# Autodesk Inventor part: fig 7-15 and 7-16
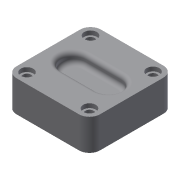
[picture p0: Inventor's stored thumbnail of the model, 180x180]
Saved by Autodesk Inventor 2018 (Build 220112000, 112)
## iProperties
Shininess: 77.0
Angle Display Precision: 2
Document Length Units: 11269
Document Angle Units: 11279
Document Time Units: 11290
Document Mass Units: 11283
Document Length Units Precision: 3
Document Angle Units Precision: 2
Created: 2001-12
Part Number: fig 7-15 and 7-16
Document SubType Name: Modeling
Designer: Renu Muthoo
Density: 1 g/cm^3
Material: Generic
Appearance: Default
Density: 0.0
Volumn: 0.0
Area: 0.0
PropertySet Name: Model Information
Control State: 0
Master: False
Checked Out: False
Author: Renu Muthoo
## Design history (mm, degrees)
sketch "Sketch1"
  geometry: L1 (-20, 20)-(20, 20); L2 (20, 20)-(20, -20.5); L3 (20, -20.5)-(-20, -20.5); L4 (-20, -20.5)-(-20, 20); 1 further point
  constraints: 8 end point, 2 parallel, 1 horizontal, 1 perpendicular, 1 other
  dimensions: "d0" = 40 distance of L1.start L1.end; "d1" = 40.5 distance of L3.end L1.start; "d100" = 20 distance from line of L4 point (0, 0); "d101" = 20 distance from line of L1 point (0, 0)
extrude "Extrusion1" new body sketch "Sketch1" distance "d2" = 15; taper "d3" = 0 deg
workplane "Work Plane1"
workplane "Work Plane2"
workplane "Work Plane3"
workplane "Work Plane4"
fillet "Fillet1" dims "d32" = 5
hole "Hole3" diameter "d66" = 4; stored, may be unused: countersink angle "d70" = 90 deg, drill point angle "d72" = 118 deg; dims "d64" = 10, "d65" = 10, "d67" = 6, "d68" = 6, "d69" = 2, "d71" = 8
hole "Hole4" diameter "d75" = 4; stored, may be unused: countersink angle "d79" = 90 deg, drill point angle "d81" = 118 deg; dims "d73" = 10, "d74" = 10, "d76" = 6, "d77" = 6, "d78" = 2, "d80" = 8
hole "Hole5" diameter "d84" = 4; stored, may be unused: countersink angle "d88" = 90 deg, drill point angle "d90" = 118 deg; dims "d82" = 10, "d83" = 10, "d85" = 6, "d86" = 6, "d87" = 2, "d89" = 8
hole "Hole6" diameter "d93" = 4; stored, may be unused: countersink angle "d97" = 90 deg, drill point angle "d99" = 118 deg; dims "d91" = 10, "d92" = 10, "d94" = 6, "d95" = 6, "d96" = 2, "d98" = 8
fillet "Fillet2" dims "d61" = 2
body "Solid1"
sketch "Sketch8"
  geometry: L1 (-9.844, 1.64)-(1.983, -10.187); L2 (10.469, -1.701)-(-1.358, 10.126); A1 r 6 centre (-5.601, 5.883) between (-1.358, 10.126) and (-9.844, 1.64); A2 r 6 centre (6.226, -5.944) between (1.983, -10.187) and (10.469, -1.701)
  constraints: 4 end point, 4 point on circle, 4 tangent, 2 centre point, 1 parallel
  dimensions: "d29" = 6 radius of A2
extrude "Extrusion2" cut sketch "Sketch8" distance "d30" = 5; taper "d31" = 0 deg
